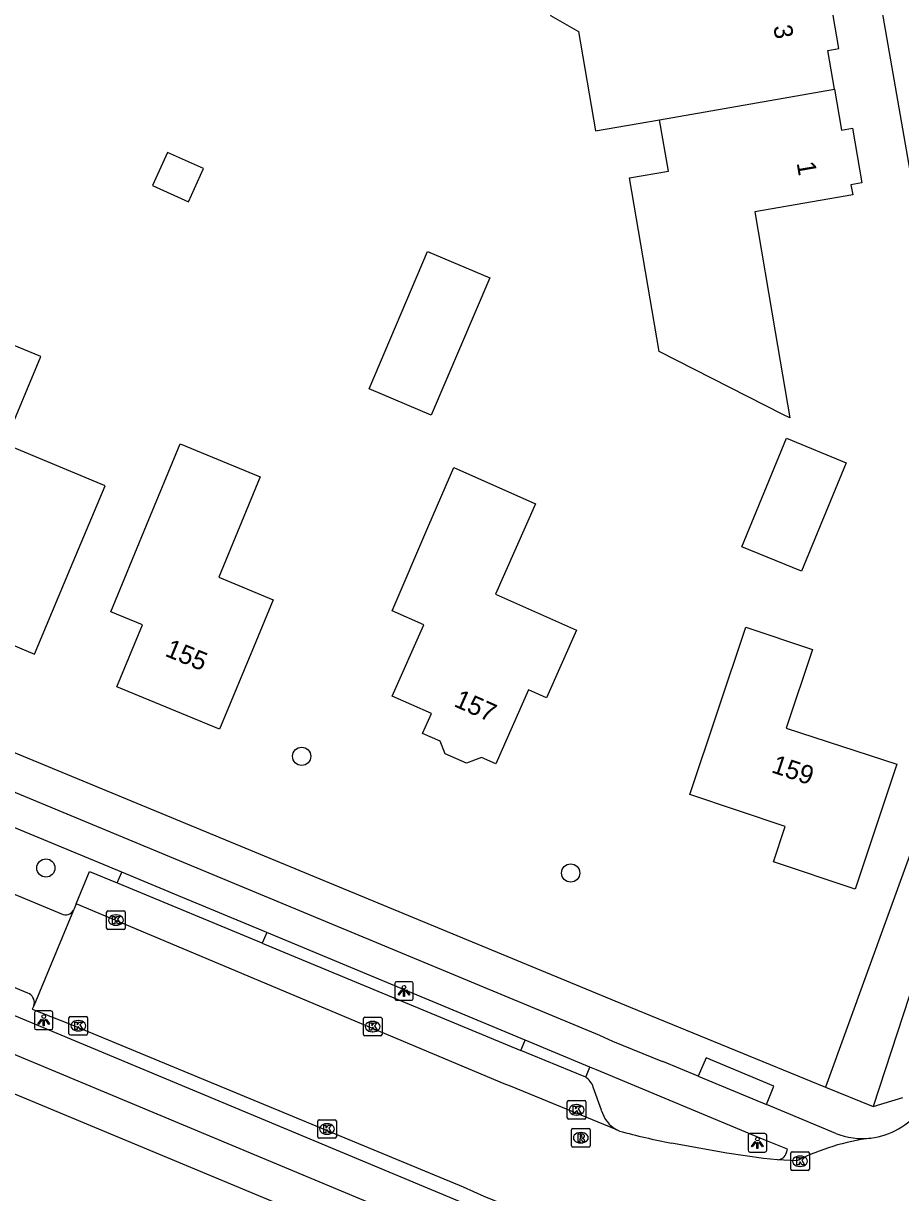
# Model space of a CAD drawing. Extents: x 162880 to 165536, y 384011 to 385179.
# Drawn here: x 163826.9 to 163874, y 384559.2 to 384622 of the extents above; entities that cross this region are included whole.
import ezdxf

# ---------------------------------------------------------------- set-up
doc = ezdxf.new("R2010")
doc.units = 0
for name, color, linetype in [('IMGEO_Boom', 7, 'Continuous'), ('IMGEO_Fietspad_gesloten', 7, 'Continuous'), ('IMGEO_Groenvoorziening', 7, 'Continuous'), ('IMGEO_Kolk', 7, 'Continuous'), ('IMGEO_Lichtpunt', 7, 'Continuous'), ('IMGEO_Pand', 7, 'Continuous'), ('IMGEO_Pand_nummerreeks', 7, 'Continuous'), ('IMGEO_Parkeervlak_open', 7, 'Continuous'), ('IMGEO_Rijbaan_lokaal_gesloten', 7, 'Continuous'), ('IMGEO_Rijbaan_lokaal_open', 7, 'Continuous'), ('IMGEO_Rioolput', 7, 'Continuous'), ('IMGEO_Voetpad_open', 7, 'Continuous')]:
    doc.layers.add(name, color=color, linetype=linetype)

msp = doc.modelspace()

# ---------------------------------------------------------------- linework, layer by layer
at = {"layer": 'IMGEO_Boom'}
for centre in [(163841.869, 384582.666), (163828.133, 384576.665), (163856.315, 384576.397)]:
    msp.add_circle(centre, 0.489, dxfattribs=at)
at = {"layer": 'IMGEO_Fietspad_gesloten'}
for points in [[(163863.164, 384565.488), (163861.273, 384566.274), (163861.262, 384566.252), (163858.577, 384567.341), (163857.889, 384567.668), (163800.004, 384591.714)], [(163861.127, 384552.196), (163860.669, 384552.399), (163850.38, 384556.646), (163849.232, 384557.122), (163812.107, 384572.625), (163809.467, 384573.741), (163807.29, 384574.754), (163793.302, 384581.295), (163792.531, 384581.666), (163785.49, 384584.993)], [(163832.206, 384576.442), (163819.328, 384581.787)], [(163859.262, 384555.12), (163858.285, 384555.496), (163851.016, 384558.475), (163850.263, 384558.782), (163812.861, 384574.404), (163810.259, 384575.54), (163808.258, 384576.447), (163799.554, 384580.523)], [(163839.991, 384573.205), (163836.514, 384574.654), (163835.682, 384574.999), (163832.206, 384576.442)], [(163853.868, 384567.425), (163839.991, 384573.205)], [(163857.353, 384565.973), (163853.868, 384567.425)], [(163867.909, 384561.378), (163867.958, 384561.554), (163866.718, 384562.057), (163857.71, 384565.826), (163857.353, 384565.973)], [(163863.164, 384565.488), (163866.829, 384563.965)], [(163870.554, 384562.408), (163866.829, 384563.965)]]:
    msp.add_lwpolyline(points, dxfattribs=at)
for centre, radius, start, end in [((163871.989, 384565.997), 3.865, 248.19766, 276.70853), ((163867.418, 384561.499), 0.506, 270.23338, 346.19483)]:
    msp.add_arc(centre, radius, start, end, dxfattribs=at)
at = {"layer": 'IMGEO_Groenvoorziening'}
msp.add_lwpolyline([(163876.394, 384603.445), (163877.092, 384596.073), (163877.72, 384586.145), (163870.006, 384564.899)], dxfattribs=at)
at = {"layer": 'IMGEO_Kolk'}
for p, q in [((163831.393, 384573.44), (163831.393, 384574.292)), ((163831.468, 384574.366), (163832.32, 384574.366)), ((163831.881, 384574.146), (163831.906, 384574.146)), ((163832.394, 384574.292), (163832.394, 384573.44)), ((163832.32, 384573.366), (163831.468, 384573.366)), ((163831.904, 384573.586), (163831.879, 384573.586)), ((163829.371, 384567.765), (163829.371, 384568.617)), ((163829.446, 384568.691), (163830.298, 384568.691)), ((163829.859, 384568.471), (163829.884, 384568.471)), ((163830.372, 384568.617), (163830.372, 384567.765)), ((163845.187, 384567.72), (163845.187, 384568.572)), ((163845.262, 384568.646), (163846.114, 384568.646)), ((163845.675, 384568.426), (163845.7, 384568.426)), ((163846.188, 384568.572), (163846.188, 384567.72)), ((163830.298, 384567.691), (163829.446, 384567.691)), ((163829.882, 384567.911), (163829.857, 384567.911)), ((163845.698, 384567.866), (163845.673, 384567.866)), ((163846.114, 384567.646), (163845.262, 384567.646)), ((163856.137, 384563.247), (163856.137, 384564.099)), ((163856.212, 384564.173), (163857.064, 384564.173)), ((163856.625, 384563.953), (163856.65, 384563.953)), ((163857.138, 384564.099), (163857.138, 384563.247)), ((163856.648, 384563.393), (163856.623, 384563.393)), ((163842.732, 384562.218), (163842.732, 384563.07)), ((163842.807, 384563.144), (163843.659, 384563.144)), ((163843.22, 384562.924), (163843.245, 384562.924)), ((163843.733, 384563.07), (163843.733, 384562.218)), ((163857.064, 384563.173), (163856.212, 384563.173)), ((163843.659, 384562.144), (163842.807, 384562.144)), ((163843.243, 384562.364), (163843.218, 384562.364)), ((163868.213, 384561.414), (163869.065, 384561.414)), ((163868.138, 384560.488), (163868.138, 384561.34)), ((163868.626, 384561.194), (163868.651, 384561.194)), ((163869.139, 384561.34), (163869.139, 384560.488)), ((163869.065, 384560.414), (163868.213, 384560.414)), ((163868.649, 384560.634), (163868.624, 384560.634))]:
    msp.add_line(p, q, dxfattribs=at)
for points in [[(163831.393, 384573.44), (163831.393, 384574.292)], [(163831.468, 384574.366), (163832.32, 384574.366)], [(163831.714, 384574.066), (163831.837, 384574.066), (163831.837, 384573.915), (163831.967, 384574.066), (163832.131, 384574.066), (163831.985, 384573.915), (163832.138, 384573.666), (163831.986, 384573.666), (163831.901, 384573.83), (163831.837, 384573.763), (163831.837, 384573.666), (163831.714, 384573.666), (163831.714, 384574.066)], [(163832.394, 384574.292), (163832.394, 384573.44)], [(163832.32, 384573.366), (163831.468, 384573.366)], [(163829.371, 384567.765), (163829.371, 384568.617)], [(163829.446, 384568.691), (163830.298, 384568.691)], [(163829.692, 384568.391), (163829.815, 384568.391), (163829.815, 384568.24), (163829.945, 384568.391), (163830.109, 384568.391), (163829.963, 384568.24), (163830.116, 384567.991), (163829.964, 384567.991), (163829.879, 384568.155), (163829.815, 384568.088), (163829.815, 384567.991), (163829.692, 384567.991), (163829.692, 384568.391)], [(163830.372, 384568.617), (163830.372, 384567.765)], [(163845.187, 384567.72), (163845.187, 384568.572)], [(163845.262, 384568.646), (163846.114, 384568.646)], [(163845.508, 384568.346), (163845.631, 384568.346), (163845.631, 384568.195), (163845.761, 384568.346), (163845.925, 384568.346), (163845.779, 384568.195), (163845.932, 384567.946), (163845.78, 384567.946), (163845.695, 384568.11), (163845.631, 384568.043), (163845.631, 384567.946), (163845.508, 384567.946), (163845.508, 384568.346)], [(163846.188, 384568.572), (163846.188, 384567.72)], [(163830.298, 384567.691), (163829.446, 384567.691)], [(163846.114, 384567.646), (163845.262, 384567.646)], [(163856.137, 384563.247), (163856.137, 384564.099)], [(163856.212, 384564.173), (163857.064, 384564.173)], [(163857.138, 384564.099), (163857.138, 384563.247)], [(163856.458, 384563.873), (163856.581, 384563.873), (163856.581, 384563.722), (163856.711, 384563.873), (163856.875, 384563.873), (163856.729, 384563.722), (163856.882, 384563.473), (163856.73, 384563.473), (163856.645, 384563.637), (163856.581, 384563.57), (163856.581, 384563.473), (163856.458, 384563.473), (163856.458, 384563.873)], [(163842.732, 384562.218), (163842.732, 384563.07)], [(163842.807, 384563.144), (163843.659, 384563.144)], [(163843.053, 384562.844), (163843.176, 384562.844), (163843.176, 384562.693), (163843.306, 384562.844), (163843.47, 384562.844), (163843.324, 384562.693), (163843.477, 384562.444), (163843.325, 384562.444), (163843.24, 384562.608), (163843.176, 384562.541), (163843.176, 384562.444), (163843.053, 384562.444), (163843.053, 384562.844)], [(163843.733, 384563.07), (163843.733, 384562.218)], [(163857.064, 384563.173), (163856.212, 384563.173)], [(163843.659, 384562.144), (163842.807, 384562.144)], [(163868.213, 384561.414), (163869.065, 384561.414)], [(163868.138, 384560.488), (163868.138, 384561.34)], [(163868.459, 384561.114), (163868.582, 384561.114), (163868.582, 384560.963), (163868.712, 384561.114), (163868.876, 384561.114), (163868.73, 384560.963), (163868.883, 384560.714), (163868.731, 384560.714), (163868.646, 384560.878), (163868.582, 384560.811), (163868.582, 384560.714), (163868.459, 384560.714), (163868.459, 384561.114)], [(163869.139, 384561.34), (163869.139, 384560.488)], [(163869.065, 384560.414), (163868.213, 384560.414)]]:
    msp.add_lwpolyline(points, dxfattribs=at)
for centre, start, end in [((163831.47, 384574.29), 91.55205, 178.44795), ((163831.47, 384574.29), 91.55205, 178.44795), ((163832.318, 384574.29), 1.55205, 88.44795), ((163832.318, 384574.29), 1.55205, 88.44795), ((163831.47, 384573.442), 181.55205, 268.44795), ((163831.47, 384573.442), 181.55205, 268.44795), ((163832.318, 384573.442), 271.55205, 358.44795), ((163832.318, 384573.442), 271.55205, 358.44795), ((163829.448, 384568.615), 91.55205, 178.44795), ((163829.448, 384568.615), 91.55205, 178.44795), ((163830.296, 384568.615), 1.55205, 88.44795), ((163830.296, 384568.615), 1.55205, 88.44795), ((163845.264, 384568.57), 91.55205, 178.44795), ((163845.264, 384568.57), 91.55205, 178.44795), ((163846.112, 384568.57), 1.55205, 88.44795), ((163846.112, 384568.57), 1.55205, 88.44795), ((163829.448, 384567.767), 181.55205, 268.44795), ((163829.448, 384567.767), 181.55205, 268.44795), ((163830.296, 384567.767), 271.55205, 358.44795), ((163830.296, 384567.767), 271.55205, 358.44795), ((163845.264, 384567.722), 181.55205, 268.44795), ((163845.264, 384567.722), 181.55205, 268.44795), ((163846.112, 384567.722), 271.55205, 358.44795), ((163846.112, 384567.722), 271.55205, 358.44795), ((163856.214, 384564.097), 91.55205, 178.44795), ((163856.214, 384564.097), 91.55205, 178.44795), ((163857.062, 384564.097), 1.55205, 88.44795), ((163857.062, 384564.097), 1.55205, 88.44795), ((163842.809, 384563.068), 91.55205, 178.44795), ((163842.809, 384563.068), 91.55205, 178.44795), ((163843.657, 384563.068), 1.55205, 88.44795), ((163843.657, 384563.068), 1.55205, 88.44795), ((163856.214, 384563.249), 181.55205, 268.44795), ((163856.214, 384563.249), 181.55205, 268.44795), ((163857.062, 384563.249), 271.55205, 358.44795), ((163857.062, 384563.249), 271.55205, 358.44795), ((163842.809, 384562.22), 181.55205, 268.44795), ((163842.809, 384562.22), 181.55205, 268.44795), ((163843.657, 384562.22), 271.55205, 358.44795), ((163843.657, 384562.22), 271.55205, 358.44795), ((163868.215, 384561.338), 91.55205, 178.44795), ((163868.215, 384561.338), 91.55205, 178.44795), ((163869.063, 384561.338), 1.55205, 88.44795), ((163869.063, 384561.338), 1.55205, 88.44795), ((163868.215, 384560.49), 181.55205, 268.44795), ((163868.215, 384560.49), 181.55205, 268.44795), ((163869.063, 384560.49), 271.55205, 358.44795), ((163869.063, 384560.49), 271.55205, 358.44795)]:
    msp.add_arc(centre, 0.0765, start, end, dxfattribs=at)
for centre, major_axis, ratio, start_param, end_param in [((163831.88, 384573.866), (-0.387, 0.002), 0.722429, 4.712389, 7.853982), ((163831.905, 384573.866), (-0.39, 0.002), 0.717154, 1.570796, 4.712389), ((163829.858, 384568.191), (-0.387, 0.002), 0.722429, 4.712389, 7.853982), ((163829.883, 384568.191), (-0.39, 0.002), 0.717154, 1.570796, 4.712389), ((163845.674, 384568.146), (-0.387, 0.002), 0.722429, 4.712389, 7.853982), ((163845.699, 384568.146), (-0.39, 0.002), 0.717154, 1.570796, 4.712389), ((163856.624, 384563.673), (-0.387, 0.002), 0.722429, 4.712389, 7.853982), ((163856.649, 384563.673), (-0.39, 0.002), 0.717154, 1.570796, 4.712389), ((163843.219, 384562.644), (-0.387, 0.002), 0.722429, 4.712389, 7.853982), ((163843.244, 384562.644), (-0.39, 0.002), 0.717154, 1.570796, 4.712389), ((163868.625, 384560.914), (-0.387, 0.002), 0.722429, 4.712389, 7.853982), ((163868.65, 384560.914), (-0.39, 0.002), 0.717154, 1.570796, 4.712389)]:
    msp.add_ellipse(centre, major_axis=major_axis, ratio=ratio, start_param=start_param, end_param=end_param, dxfattribs=at)
at = {"layer": 'IMGEO_Lichtpunt'}
for p, q in [((163846.868, 384570.463), (163846.868, 384569.656)), ((163846.868, 384570.463), (163846.868, 384569.656)), ((163847.77, 384570.558), (163846.962, 384570.558)), ((163847.77, 384570.558), (163846.962, 384570.558)), ((163847.864, 384569.656), (163847.864, 384570.463)), ((163847.864, 384569.656), (163847.864, 384570.463)), ((163846.962, 384569.562), (163847.77, 384569.562)), ((163846.962, 384569.562), (163847.77, 384569.562)), ((163828.42, 384568.984), (163827.612, 384568.984)), ((163828.42, 384568.984), (163827.612, 384568.984)), ((163827.518, 384568.889), (163827.518, 384568.082)), ((163827.518, 384568.889), (163827.518, 384568.082)), ((163828.514, 384568.082), (163828.514, 384568.889)), ((163828.514, 384568.082), (163828.514, 384568.889)), ((163827.612, 384567.988), (163828.42, 384567.988)), ((163827.612, 384567.988), (163828.42, 384567.988)), ((163865.849, 384562.306), (163865.849, 384561.499)), ((163865.849, 384562.306), (163865.849, 384561.499)), ((163866.751, 384562.401), (163865.943, 384562.401)), ((163866.751, 384562.401), (163865.943, 384562.401)), ((163866.845, 384561.499), (163866.845, 384562.306)), ((163866.845, 384561.499), (163866.845, 384562.306)), ((163865.943, 384561.405), (163866.751, 384561.405)), ((163865.943, 384561.405), (163866.751, 384561.405))]:
    msp.add_line(p, q, dxfattribs=at)
for points in [[(163847.242, 384570.127), (163847.281, 384570.099), (163847.093, 384569.837), (163847.055, 384569.864), (163847.242, 384570.127)], [(163847.344, 384570.079), (163847.391, 384570.079), (163847.391, 384569.757), (163847.344, 384569.757), (163847.344, 384570.079)], [(163847.454, 384570.099), (163847.492, 384570.126), (163847.679, 384569.864), (163847.64, 384569.836), (163847.454, 384570.099)], [(163827.892, 384568.553), (163827.931, 384568.525), (163827.743, 384568.263), (163827.705, 384568.29), (163827.892, 384568.553)], [(163827.994, 384568.505), (163828.041, 384568.505), (163828.041, 384568.183), (163827.994, 384568.183), (163827.994, 384568.505)], [(163828.104, 384568.525), (163828.142, 384568.552), (163828.329, 384568.29), (163828.29, 384568.262), (163828.104, 384568.525)], [(163866.223, 384561.97), (163866.262, 384561.942), (163866.074, 384561.68), (163866.036, 384561.707), (163866.223, 384561.97)], [(163866.325, 384561.922), (163866.372, 384561.922), (163866.372, 384561.6), (163866.325, 384561.6), (163866.325, 384561.922)], [(163866.435, 384561.942), (163866.473, 384561.969), (163866.66, 384561.707), (163866.621, 384561.679), (163866.435, 384561.942)]]:
    msp.add_lwpolyline(points, dxfattribs=at)
for centre in [(163847.367, 384570.261), (163828.017, 384568.687), (163866.348, 384562.104)]:
    msp.add_circle(centre, 0.0994, dxfattribs=at)
for centre, start, end in [((163846.962, 384570.463), 90, 180), ((163846.962, 384570.463), 90, 180), ((163847.77, 384570.463), 0, 90), ((163847.77, 384570.463), 0, 90), ((163846.962, 384569.656), 180, 270), ((163846.962, 384569.656), 180, 270), ((163847.77, 384569.656), 270, 0), ((163847.77, 384569.656), 270, 360), ((163827.612, 384568.889), 90, 180), ((163827.612, 384568.889), 90, 180), ((163828.42, 384568.889), 0, 90), ((163828.42, 384568.889), 0, 90), ((163827.612, 384568.082), 180, 270), ((163827.612, 384568.082), 180, 270), ((163828.42, 384568.082), 270, 0), ((163828.42, 384568.082), 270, 360), ((163865.943, 384562.306), 90, 180), ((163865.943, 384562.306), 90, 180), ((163866.751, 384562.306), 0, 90), ((163866.751, 384562.306), 0, 90), ((163865.943, 384561.499), 180, 270), ((163865.943, 384561.499), 180, 270), ((163866.751, 384561.499), 270, 0), ((163866.751, 384561.499), 270, 360)]:
    msp.add_arc(centre, 0.0946, start, end, dxfattribs=at)
at = {"layer": 'IMGEO_Pand'}
for points in [[(163870.492, 384618.515), (163870.137, 384620.591), (163870.727, 384620.692), (163870.225, 384623.634), (163869.633, 384623.533), (163869.542, 384624.064), (163864.295, 384623.168), (163863.774, 384626.22)], [(163854.849, 384624.685), (163855.228, 384622.467), (163856.732, 384621.6), (163857.643, 384616.277), (163861.093, 384616.868)], [(163870.492, 384618.515), (163870.869, 384616.31), (163871.46, 384616.411), (163871.963, 384613.469), (163871.373, 384613.369), (163871.465, 384612.827), (163866.201, 384611.925), (163867.304, 384605.477), (163868.096, 384600.847), (163867.717, 384601.039), (163861.073, 384604.409), (163859.472, 384613.75), (163861.565, 384614.109), (163861.093, 384616.868)], [(163861.093, 384616.868), (163870.492, 384618.515)], [(163836.594, 384614.24), (163834.672, 384615.109), (163833.867, 384613.328), (163835.789, 384612.459), (163836.594, 384614.24)], [(163851.971, 384608.368), (163848.824, 384600.995), (163845.488, 384602.418), (163848.635, 384609.792), (163851.971, 384608.368)], [(163829.456, 384592.77), (163831.309, 384597.197), (163825.912, 384599.455), (163827.855, 384604.15), (163824.577, 384605.491), (163823.415, 384602.716), (163821.484, 384598.103), (163824.242, 384596.94), (163821.638, 384590.621), (163823.27, 384589.934), (163823.592, 384589.337), (163825.258, 384588.638), (163825.909, 384588.838), (163827.525, 384588.157), (163829.456, 384592.77)], [(163867.905, 384599.752), (163871.109, 384598.438), (163868.72, 384592.615), (163865.516, 384593.929), (163867.905, 384599.752)], [(163839.643, 384597.677), (163837.418, 384592.285), (163840.338, 384591.08), (163839.407, 384588.824), (163837.466, 384584.12), (163831.941, 384586.4), (163833.316, 384589.733), (163831.619, 384590.434), (163833.536, 384595.078), (163835.341, 384599.453), (163839.643, 384597.677)], [(163850.038, 384598.178), (163854.428, 384596.233), (163852.278, 384591.378), (163856.637, 384589.447), (163855.027, 384585.811), (163854.051, 384586.243), (163852.29, 384582.267), (163851.532, 384582.603), (163850.731, 384582.294), (163849.573, 384582.807), (163849.316, 384583.472), (163848.369, 384583.892), (163848.846, 384584.97), (163846.735, 384585.905), (163848.433, 384589.737), (163846.731, 384590.491), (163848.707, 384595.085), (163850.038, 384598.178)], [(163869.311, 384588.413), (163867.897, 384584.178), (163873.83, 384582.243), (163871.592, 384575.537), (163867.21, 384577), (163867.843, 384578.897), (163862.72, 384580.607), (163865.725, 384589.609), (163869.311, 384588.413)]]:
    msp.add_lwpolyline(points, dxfattribs=at)
at = {"layer": 'IMGEO_Parkeervlak_open'}
for points in [[(163829.76, 384574.742), (163830.47, 384576.473), (163831.965, 384575.865)], [(163839.752, 384572.631), (163853.635, 384566.864)], [(163857.965, 384563.656), (163857.531, 384564.9)]]:
    msp.add_lwpolyline(points, dxfattribs=at)
for centre, radius, start, end in [((163856.579, 384564.576), 1.006, 18.81425, 57.17895), ((163859.635, 384564.117), 1.733, 195.44295, 241.41375)]:
    msp.add_arc(centre, radius, start, end, dxfattribs=at)
at = {"layer": 'IMGEO_Rijbaan_lokaal_gesloten'}
for points in [[(163829.76, 384574.742), (163829.65, 384574.473), (163829.619, 384574.405)], [(163858.806, 384562.596), (163853.078, 384564.952), (163852.754, 384565.074), (163829.76, 384574.742)], [(163829.619, 384574.405), (163827.486, 384569.264)], [(163827.486, 384569.264), (163827.398, 384569.076), (163829.395, 384568.286), (163850.541, 384559.54), (163851.656, 384559.039), (163855.569, 384557.446), (163859.48, 384555.824)], [(163858.936, 384562.532), (163858.806, 384562.596)], [(163867.42, 384560.993), (163866.678, 384561.067), (163864.713, 384561.35), (163861.733, 384561.877)], [(163868.47, 384560.939), (163867.42, 384560.993)]]:
    msp.add_lwpolyline(points, dxfattribs=at)
for centre, radius, start, end in [((163871.996, 384565.997), 3.865, 276.61602, 323.38334), ((163871.286, 384608.968), 48.05, 255.10704, 258.53298), ((163874.111, 384549.641), 12.628, 97.59863, 116.53179)]:
    msp.add_arc(centre, radius, start, end, dxfattribs=at)
at = {"layer": 'IMGEO_Rijbaan_lokaal_open'}
for points in [[(163825.512, 384575.636), (163828.976, 384574.206)], [(163827.165, 384569.946), (163823.757, 384571.36)], [(163827.486, 384569.264), (163827.507, 384569.349)]]:
    msp.add_lwpolyline(points, dxfattribs=at)
for centre, radius, start, end in [((163829.194, 384574.641), 0.486, 243.41564, 330.97757), ((163826.964, 384569.435), 0.549, 351.02985, 68.58387)]:
    msp.add_arc(centre, radius, start, end, dxfattribs=at)
at = {"layer": 'IMGEO_Rioolput'}
for p, q in [((163856.436, 384562.674), (163857.288, 384562.674)), ((163856.361, 384561.748), (163856.361, 384562.6)), ((163856.849, 384562.454), (163856.874, 384562.454)), ((163857.362, 384562.6), (163857.362, 384561.748)), ((163857.288, 384561.674), (163856.436, 384561.674)), ((163856.872, 384561.894), (163856.847, 384561.894))]:
    msp.add_line(p, q, dxfattribs=at)
for points in [[(163856.436, 384562.674), (163857.288, 384562.674)], [(163856.361, 384561.748), (163856.361, 384562.6)], [(163856.95, 384562.372), (163856.698, 384562.374), (163856.698, 384561.974)], [(163856.698, 384561.974), (163856.822, 384561.974), (163856.822, 384562.136), (163856.833, 384562.136)], [(163856.876, 384562.293), (163856.822, 384562.293), (163856.822, 384562.212)], [(163856.822, 384562.212), (163856.874, 384562.212)], [(163856.88, 384562.107), (163856.951, 384561.974), (163857.091, 384561.974), (163857.026, 384562.1)], [(163857.362, 384562.6), (163857.362, 384561.748)], [(163857.288, 384561.674), (163856.436, 384561.674)]]:
    msp.add_lwpolyline(points, dxfattribs=at)
for centre, radius, start, end in [((163856.438, 384562.598), 0.0765, 91.55205, 178.44795), ((163856.438, 384562.598), 0.0765, 91.55205, 178.44795), ((163857.286, 384562.598), 0.0765, 1.55205, 88.44795), ((163857.286, 384562.598), 0.0765, 1.55205, 88.44795), ((163856.832, 384562.083), 0.0533, 26.02933, 88.69889), ((163856.858, 384562.401), 0.19, 274.7715, 282.96867), ((163856.882, 384562.197), 0.0964, 77.00612, 93.18647), ((163856.896, 384562.254), 0.0378, 276.66336, 79.67722), ((163856.949, 384562.262), 0.109, 350.36119, 89.41601), ((163856.947, 384562.262), 0.112, 277.58423, 350.98172), ((163856.931, 384562.047), 0.108, 29.51342, 73.79051), ((163856.438, 384561.75), 0.0765, 181.55205, 268.44795), ((163856.438, 384561.75), 0.0765, 181.55205, 268.44795), ((163857.286, 384561.75), 0.0765, 271.55205, 358.44795), ((163857.286, 384561.75), 0.0765, 271.55205, 358.44795)]:
    msp.add_arc(centre, radius, start, end, dxfattribs=at)
for centre, major_axis, ratio, start_param, end_param in [((163856.848, 384562.174), (-0.387, 0.002), 0.722429, 4.712389, 7.853982), ((163856.873, 384562.174), (-0.39, 0.002), 0.717154, 1.570796, 4.712389)]:
    msp.add_ellipse(centre, major_axis=major_axis, ratio=ratio, start_param=start_param, end_param=end_param, dxfattribs=at)
at = {"layer": 'IMGEO_Voetpad_open'}
for points in [[(163868.638, 384648.333), (163868.915, 384646.347), (163876.394, 384603.445)], [(163799.826, 384593.865), (163799.9, 384594.018), (163806.282, 384591.401), (163806.205, 384591.228), (163859.512, 384569.182), (163870.006, 384564.899)], [(163799.02, 384577.651), (163799.868, 384577.282), (163799.271, 384575.856), (163855.748, 384552.326), (163856.415, 384552.055)], [(163876.795, 384576.84), (163875.144, 384571.725), (163872.567, 384563.854)], [(163831.965, 384575.865), (163832.206, 384576.442)], [(163839.752, 384572.631), (163832.069, 384575.823), (163831.965, 384575.865)], [(163839.991, 384573.205), (163839.752, 384572.631)], [(163853.635, 384566.864), (163853.868, 384567.425)], [(163857.124, 384565.421), (163857.038, 384565.471), (163854.257, 384566.605), (163853.635, 384566.864)], [(163866.829, 384563.965), (163867.233, 384564.943), (163863.598, 384566.464), (163863.164, 384565.488)], [(163857.124, 384565.421), (163857.353, 384565.973)], [(163870.006, 384564.899), (163872.567, 384563.854)], [(163872.567, 384563.854), (163874.161, 384564.329)]]:
    msp.add_lwpolyline(points, dxfattribs=at)

# ---------------------------------------------------------------- texts
at = {"layer": 'IMGEO_Pand_nummerreeks'}
for s, rotation, p in [('3', 279.68325, (163867.196, 384621.883)), ('1', 279.69997, (163868.451, 384614.545)), ('155', 337.57554, (163834.475, 384588.081)), ('157', 336.10641, (163849.996, 384585.376)), ('159', 341.54157, (163867.049, 384581.818))]:
    msp.add_text(s, height=1, rotation=rotation, dxfattribs=at).set_placement(p)

doc.saveas('drawing.dxf')
